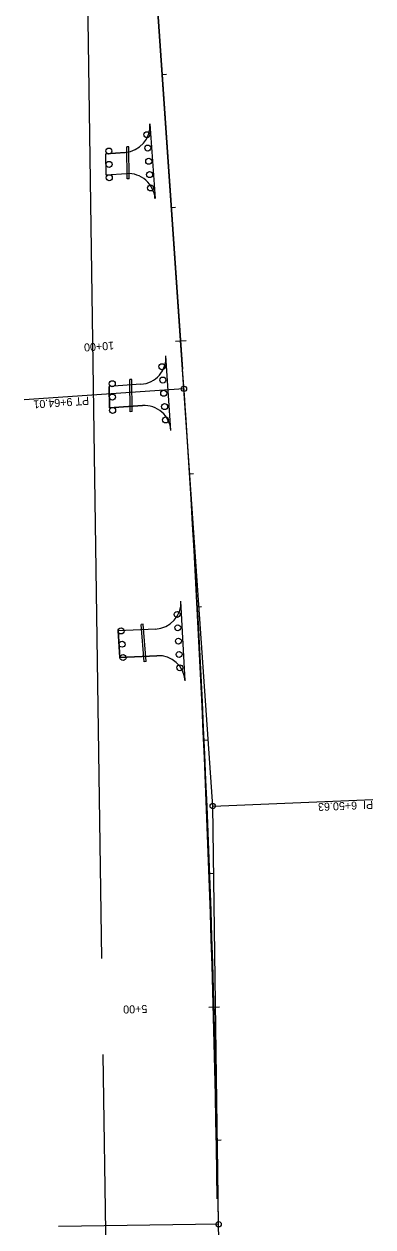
# Model space of a CAD drawing. Extents: x 1665984 to 1683035, y 227409 to 233856.
# Drawn here: x 1677298 to 1677559, y 230249 to 231150 of the extents above; entities that cross this region are included whole.
import ezdxf

# ---------------------------------------------------------------- set-up
doc = ezdxf.new("R2010")
doc.units = 0
for name, color, linetype in [('R_Horz Alg', 7, 'Continuous'), ('R_Horz Alg Annot', 7, 'Continuous'), ('R_MOT', 7, 'Continuous'), ('R_No Plot', 7, 'Continuous'), ('R_Proposed Road_Lane', 7, 'Continuous'), ('R_Water', 7, 'Continuous')]:
    doc.layers.add(name, color=color, linetype=linetype)

msp = doc.modelspace()

# ---------------------------------------------------------------- linework, layer by layer
at = {"layer": 'R_Horz Alg'}
for p, q in [((1677417.64, 230877), (1677316.59, 232344.06)), ((1677445.52, 230113.63), (1677443.59, 230250.71))]:
    msp.add_line(p, q, dxfattribs=at)
msp.add_arc((1665985.57, 230089.6), 11459.16, 0.805578, 3.940113, dxfattribs=at)
at = {"layer": 'R_Horz Alg Annot'}
for p, q in [((1677439.18, 230564.21), (1677417.64, 230877)), ((1677443.59, 230250.71), (1677439.18, 230564.21))]:
    msp.add_line(p, q, dxfattribs=at)
for points in [[(1677404.42, 231112.64), (1677401.42, 231112.44)], [(1677411.29, 231012.88), (1677408.3, 231012.67)], [(1677411.18, 230912.64), (1677419.16, 230913.19)], [(1677417.64, 230877), (1677297.92, 230868.76)], [(1677424.85, 230813.33), (1677421.86, 230813.14)], [(1677430.73, 230713.47), (1677427.74, 230713.31)], [(1677435.74, 230613.57), (1677432.75, 230613.43)], [(1677439.18, 230564.21), (1677559.08, 230569.18)], [(1677439.88, 230513.63), (1677436.88, 230513.52)], [(1677436.15, 230413.46), (1677444.14, 230413.69)], [(1677445.53, 230313.66), (1677442.53, 230313.6)], [(1677443.59, 230250.71), (1677323.6, 230249.02)]]:
    msp.add_lwpolyline(points, dxfattribs=at)
for centre in [(1677417.64, 230877), (1677439.18, 230564.21), (1677443.59, 230250.71)]:
    msp.add_circle(centre, 2, dxfattribs=at)
at = {"layer": 'R_MOT'}
for p, q in [((1677392.09, 231075.58), (1677395.94, 231019.71)), ((1677359.17, 231053.27), (1677373.51, 231054.26)), ((1677359.4, 231037.25), (1677359.17, 231053.27)), ((1677374.61, 231038.29), (1677359.4, 231037.25)), ((1677407.82, 230845.79), (1677404.06, 230901.75)), ((1677385.45, 230880.42), (1677361.7, 230878.82)), ((1677361.7, 230878.82), (1677361.93, 230862.8)), ((1677361.93, 230862.8), (1677386.52, 230864.45)), ((1677418.42, 230657.99), (1677415.37, 230717.92)), ((1677396.41, 230696.93), (1677368.25, 230695.5)), ((1677368.25, 230695.5), (1677369.73, 230675.54)), ((1677369.73, 230675.54), (1677397.43, 230676.95))]:
    msp.add_line(p, q, dxfattribs=at)
for centre in [(1677389.86, 231067.53), (1677361.39, 231055.29), (1677390.54, 231057.56), (1677361.53, 231045.29), (1677391.23, 231047.58), (1677361.68, 231035.29), (1677391.92, 231037.61), (1677392.6, 231027.63), (1677401.14, 230893.61), (1677401.8, 230883.63), (1677363.92, 230880.84), (1677402.47, 230873.65), (1677364.06, 230870.84), (1677403.14, 230863.68), (1677364.21, 230860.84), (1677403.81, 230853.7), (1677412.49, 230707.84), (1677370.5, 230695.52), (1677413, 230697.85), (1677371.24, 230685.55), (1677413.51, 230687.87), (1677371.98, 230675.57), (1677414.02, 230677.88), (1677414.52, 230667.89)]:
    msp.add_circle(centre, 2.25, dxfattribs=at)
for centre, start, end in [((1677372.14, 231074.21), 273.94011, 3.94011), ((1677375.98, 231018.34), 3.94011, 93.94011), ((1677384.11, 230900.37), 273.84002, 3.94011), ((1677387.86, 230844.5), 3.69978, 93.84002), ((1677395.4, 230716.9), 272.9093, 2.9093), ((1677398.44, 230656.98), 2.9093, 92.9093)]:
    msp.add_arc(centre, 20, start, end, dxfattribs=at)
at = {"layer": 'R_No Plot'}
for p, q in [((1677416.63, 230891.71), (1677348.03, 231887.62)), ((1677348.03, 231887.62), (1677416.63, 230891.71)), ((1677341.73, 231428.58), (1677355.91, 230449.91)), ((1677356.96, 230378.03), (1677359.83, 230180.04))]:
    msp.add_line(p, q, dxfattribs=at)
msp.add_arc((1665972.58, 230103.49), 11471.16, 0.830617, 3.940113, dxfattribs=at)
at = {"layer": 'R_Proposed Road_Lane'}
for p, q in [((1677373.51, 231054.26), (1677359.17, 231053.27)), ((1677359.4, 231037.25), (1677359.17, 231053.27)), ((1677374.61, 231038.29), (1677359.4, 231037.25)), ((1677385.45, 230880.42), (1677361.7, 230878.82)), ((1677361.93, 230862.8), (1677361.7, 230878.82)), ((1677386.52, 230864.45), (1677361.93, 230862.8)), ((1677396.41, 230696.93), (1677368.25, 230695.5)), ((1677369.73, 230675.54), (1677368.25, 230695.5)), ((1677397.43, 230676.95), (1677369.73, 230675.54))]:
    msp.add_line(p, q, dxfattribs=at)
for centre, start, end in [((1677372.14, 231074.21), 273.94011, 3.94011), ((1677375.98, 231018.34), 3.94011, 93.94011), ((1677384.11, 230900.37), 273.84002, 3.94011), ((1677387.86, 230844.5), 3.69978, 93.84002), ((1677395.4, 230716.9), 272.9093, 2.9093), ((1677398.44, 230656.98), 2.9093, 92.9093)]:
    msp.add_arc(centre, 20, start, end, dxfattribs=at)
at = {"layer": 'R_Water'}
for p, q in [((1677376.26, 231058.4), (1677374.76, 231058.38)), ((1677375.1, 231034.38), (1677374.76, 231058.38)), ((1677376.6, 231034.4), (1677376.26, 231058.4)), ((1677376.6, 231034.4), (1677375.1, 231034.38)), ((1677378.58, 230883.91), (1677377.08, 230883.89)), ((1677377.43, 230859.89), (1677377.08, 230883.89)), ((1677378.93, 230859.92), (1677378.58, 230883.91)), ((1677378.93, 230859.92), (1677377.43, 230859.89)), ((1677387.14, 230700.49), (1677385.64, 230700.38)), ((1677387.7, 230672.46), (1677385.64, 230700.38)), ((1677389.2, 230672.57), (1677387.14, 230700.49)), ((1677389.2, 230672.57), (1677387.7, 230672.46))]:
    msp.add_line(p, q, dxfattribs=at)

# ---------------------------------------------------------------- texts
at = {"layer": 'R_Horz Alg Annot'}
for s, rotation, p in [('10+00', 183.94011, (1677365.08, 230912.47)), ('PT 9+64.01', 183.94011, (1677346.35, 230871.09)), ('PI  6+50.63', 182.37285, (1677559.12, 230568.18)), ('5+00', 181.62009, (1677390.08, 230415.16))]:
    msp.add_text(s, height=6, rotation=rotation, dxfattribs=at).set_placement(p)

doc.saveas('drawing.dxf')
